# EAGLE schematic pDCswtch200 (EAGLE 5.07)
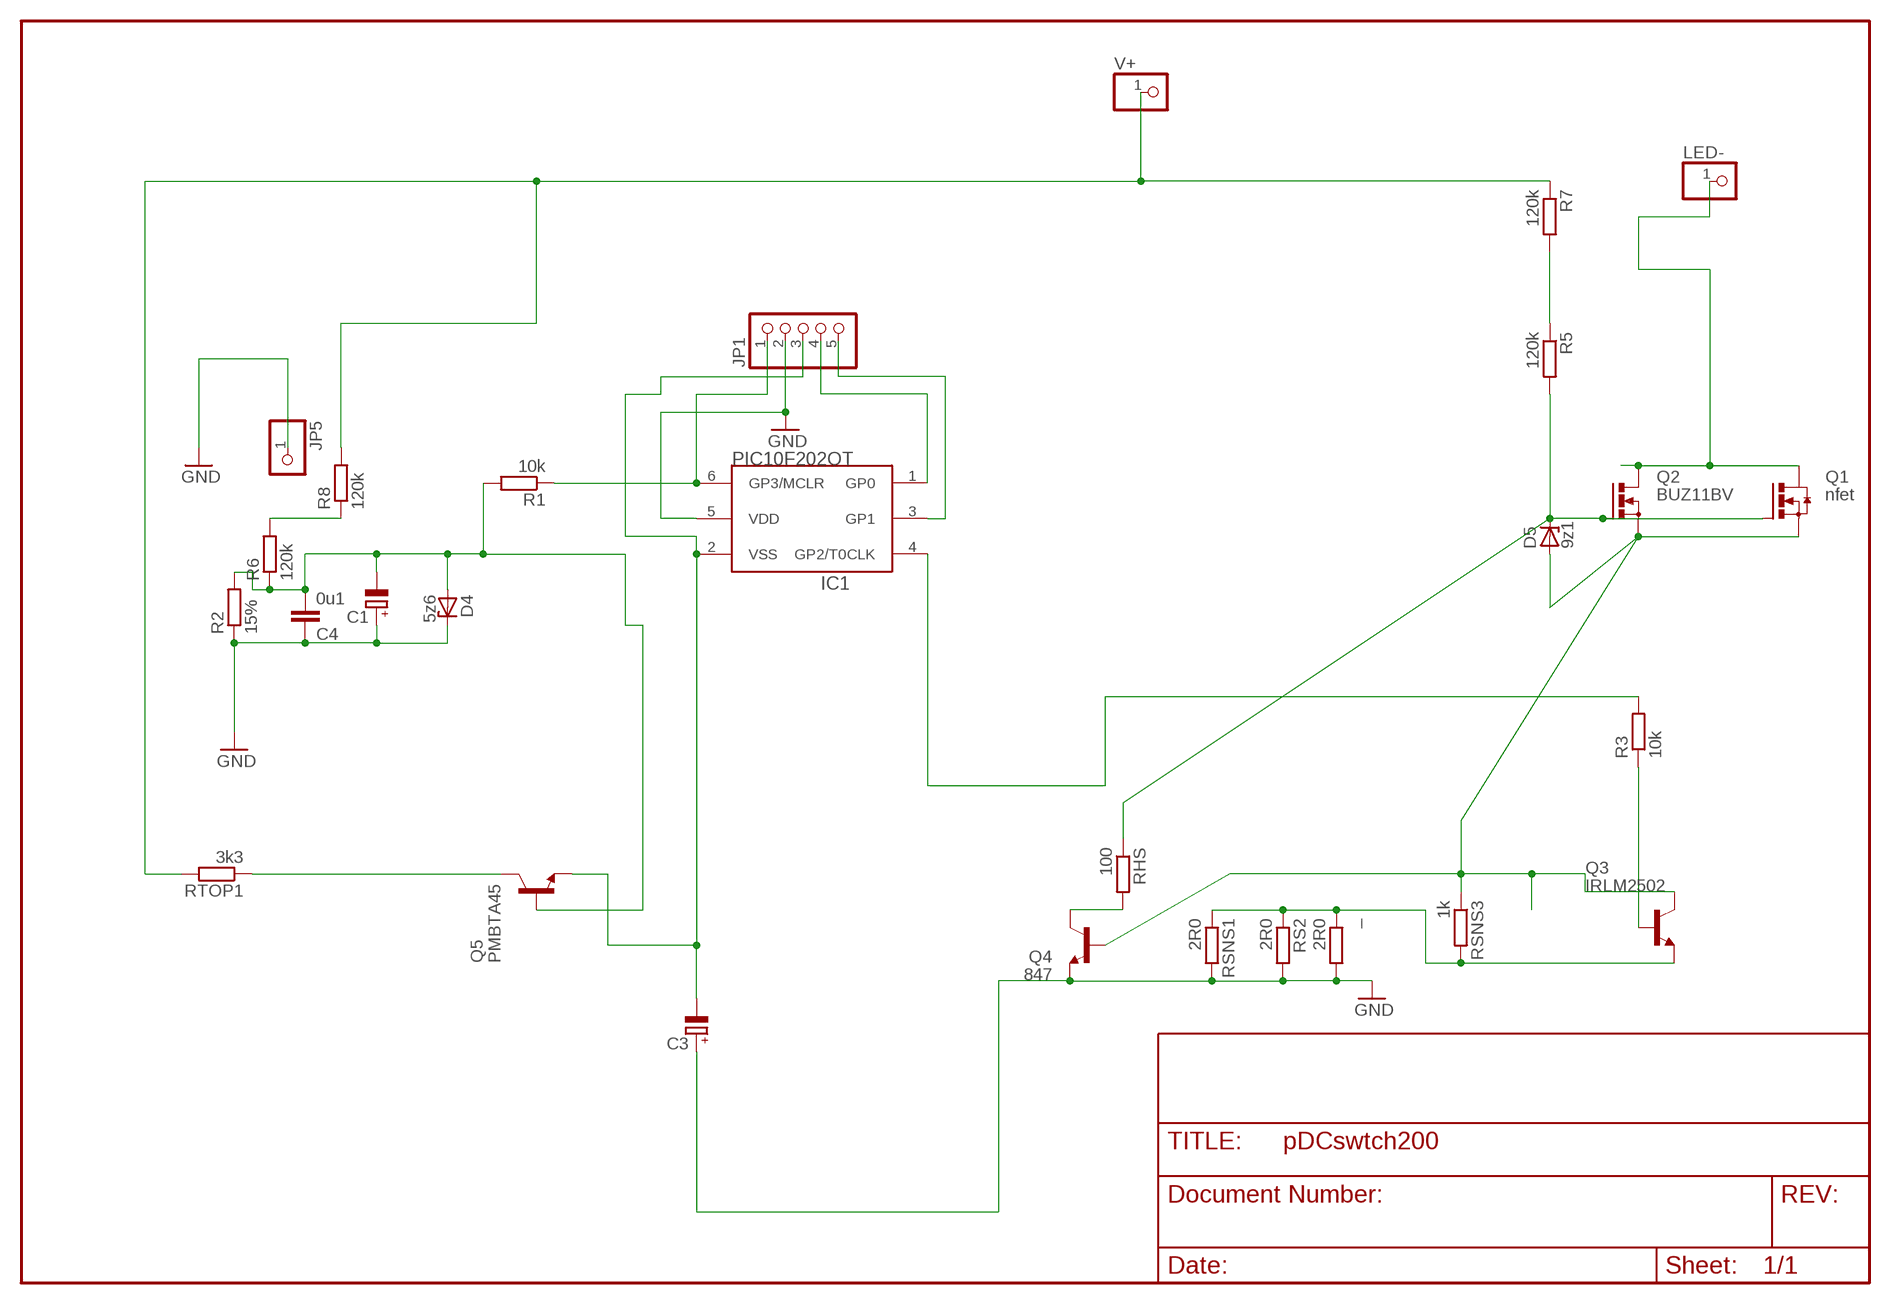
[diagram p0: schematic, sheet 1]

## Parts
_  2R0  R-EU_R1210  [R1210]
C1  CPOL-EUSMCA  [SMC_A]
C3  CPOL-EUE2,5-6E  [E2,5-6E]
C4  0u1  C-EUC0805  [C0805]
D4  5z6  ZENER-DIODESOD80C  [SOD80C]
D5  9z1  ZENER-DIODESOD80C  [SOD80C]
IC1  PIC10F202OT  [SOT23-6]
JP1  PINHD-1X5/90  [1X05/90]
JP5  PINHD-1X11MM6  [1X1MM8]
LED-  PINHD-1X11MM6  [1X1MM8]
Q1  nfet  N-HEXFET_DPAK-  [TO252]
Q2  BUZ11BV  [TO220BV]
Q3  IRLM2502  BC847ALT1SMD  [SOT23]
Q4  847  BC847ASMD  [SOT23]
Q5  PMBTA45  BC847ALT1SMD  [SOT23]
R1  10k  R-EU_R0805  [R0805]
R2  15%  R-EU_R0805  [R0805]
R3  10k  R-EU_R0805  [R0805]
R5  120k  R-EU_R1206  [R1206]
R6  120k  R-EU_R1206  [R1206]
R7  120k  R-EU_R1206  [R1206]
R8  120k  R-EU_R1206  [R1206]
RHS  100  R-EU_0204/5  [0204/5]
RS2  2R0  R-EU_R1206  [R1206]
RSNS1  2R0  R-EU_R2512  [R2512]
RSNS3  1k  R-EU_R1206  [R1206]
RTOP1  3k3  R-EU_R1206  [R1206]
V+  PINHD-1X11MM6  [1X1MM8]

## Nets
BSW1: _.1 Q3.2(E) RS2.1 RSNS1.1 RSNS3.2
C: Q5.3(C) RTOP1.1
CB: C1.- C4.2 D4.A Q5.1(B) R1.2 R2.2 R6.1
G: D5.C Q1.1(G) Q2.G R5.2 RHS.1
GND: _.2 C1.+ C3.+ C4.1 D4.C IC1.5(VDD) JP1.2 JP5.1 Q4.2(E) R2.1 RS2.2 RSNS1.2
GP2: IC1.4(GP2/T0CLK) R3.2
LED-: LED-.1 Q1.3(D) Q2.D
N$3: IC1.6(GP3/MCLR) JP1.1 R1.1
N$4: R5.1 R7.2
N$5: Q3.1(B) R3.1
N$7: Q4.3(C) RHS.2
N$9: R6.2 R8.1
N$10: IC1.1(GP0) JP1.4
N$12: IC1.3(GP1) JP1.5
S: D5.A Q1.2(S) Q2.S Q3.3(C) Q4.1(B) RSNS3.1
VPLUS: R7.1 R8.2 RTOP1.2 V+.1
VSS-: C3.- IC1.2(VSS) JP1.3 Q5.2(E)

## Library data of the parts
_ R3 R5 R7 RHS RS2 RSNS1 RSNS3 RTOP1 = rcl:R-EU_: RESISTOR, European symbol
C1 C3 = rcl:CPOL-EU: POLARIZED CAPACITOR, European symbol
C4 = rcl:C-EU: CAPACITOR, European symbol
D4 D5 = diode:ZENER-DIODE: Z-Diode
IC1 = microchip-5:PIC10F20*: uPC nW 0,25/0,5k Program Flash memory
JP1 = pinhead:PINHD-1X5: PIN HEADER
JP5 LED- V+ = pinhead:PINHD-1X1: PIN HEADER
Q1 = transistor-power:N-HEXFET_?-*: HEXFET® Power MOSFET
Q2 = transistor-power:BUZ11: N-CHANNEL MOS FET
Q3-Q5 = transistor-npn:BC847*: NPN Transistor
R1 R2 R6 R8 = rcl-2:R-EU_: RESISTOR, European symbol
